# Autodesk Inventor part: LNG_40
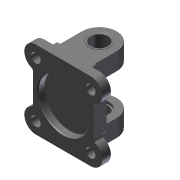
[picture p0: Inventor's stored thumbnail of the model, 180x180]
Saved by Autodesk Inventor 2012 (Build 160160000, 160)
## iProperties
Company: CAD-Verlag
Created: 2004-09
Part Number: LNG_40
Document SubType Name: Modeling
Designer: Greiling
Manufacturer: Standard
Standards Organization: Custom
Density: 1 g/cm^3
Checked By: Jürgen Kronas
Stock Number: 10-10017
Material: Standard
Übersetzungsnorm: STEP AP203
Dateiname: s:/PartAssembly/iodir/wkb1973854_no0//0//174391_SNCB_40.stp
Postprozessor: Build: 096e, Release: 9 RTM - Date: Thu 06/17/2004
Gesendete Einheiten: MILLIMETERS
Unbestimmtheit: 1.0000000000000002e-06
Author: Juergen Kronas
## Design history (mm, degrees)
feature "Basis1"
node "Volumenkörper1"
node "Volumenkörpern"
node "Oberflächenkörpern"
